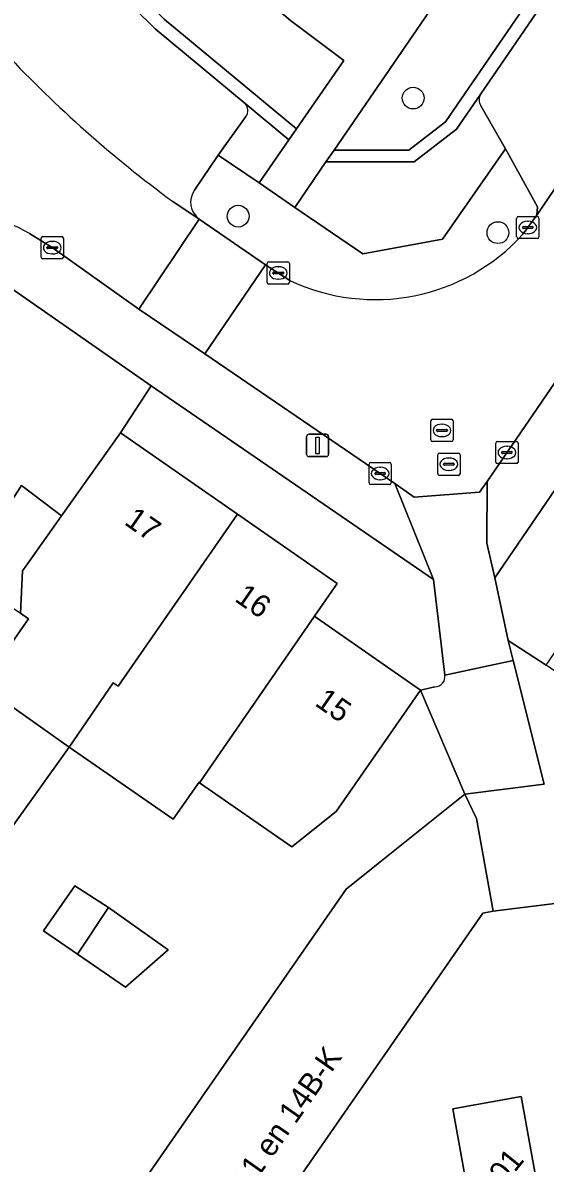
# Model space of a CAD drawing. Extents: x 159664 to 160323, y 385312 to 386115.
# Drawn here: x 160010.7 to 160034.2, y 385414.8 to 385466 of the extents above; entities that cross this region are included whole.
import ezdxf

# ---------------------------------------------------------------- set-up
doc = ezdxf.new("R2010")
doc.units = 0
for name, color, linetype in [('IMGEO_Boom', 7, 'Continuous'), ('IMGEO_Erf', 7, 'Continuous'), ('IMGEO_Groenvoorziening', 7, 'Continuous'), ('IMGEO_Haag', 7, 'Continuous'), ('IMGEO_Kolk', 7, 'Continuous'), ('IMGEO_Lichtmast', 7, 'Continuous'), ('IMGEO_Pand', 7, 'Continuous'), ('IMGEO_Pand_nummerreeks', 7, 'Continuous'), ('IMGEO_Parkeervlak_open', 7, 'Continuous'), ('IMGEO_Rijbaan_lokaal_open', 7, 'Continuous'), ('IMGEO_Rioolput', 7, 'Continuous'), ('IMGEO_Voetpad_halfverhard', 7, 'Continuous'), ('IMGEO_Voetpad_open', 7, 'Continuous')]:
    doc.layers.add(name, color=color, linetype=linetype)

msp = doc.modelspace()

# ---------------------------------------------------------------- linework, layer by layer
at = {"layer": 'IMGEO_Boom'}
for centre in [(160028.236, 385462.638), (160020.374, 385457.33), (160032.047, 385456.591)]:
    msp.add_circle(centre, 0.489, dxfattribs=at)
at = {"layer": 'IMGEO_Erf'}
for points in [[(160072.148, 385500), (160031.904, 385441.082), (160032.505, 385438.276), (160034.212, 385437.156), (160037.344, 385441.746), (160036.07, 385442.615), (160039.191, 385447.19), (160041.023, 385449.876), (160042.894, 385448.599), (160044.18, 385450.485), (160045.745, 385452.778), (160045.117, 385453.206), (160046.672, 385455.485), (160048.455, 385458.097), (160049.111, 385457.649), (160050.448, 385459.609), (160052.577, 385462.729), (160051.933, 385463.169), (160052.924, 385464.621), (160055.268, 385468.057)], [(160016.466, 385449.703), (160015.086, 385447.598), (160020.345, 385443.944), (160024.816, 385440.836), (160023.799, 385439.361), (160023.92, 385439.277), (160028.574, 385436.043), (160029.216, 385436.184)], [(160029.667, 385436.713), (160029.146, 385441.011), (160016.466, 385449.703)], [(160009.916, 385429.488), (160012.781, 385433.479), (160008.855, 385436.25), (160010.95, 385439.25), (160010.594, 385439.497)], [(160013.217, 385409.794), (160025.229, 385427.108), (160026.659, 385428.251), (160030.564, 385431.373), (160028.574, 385436.043), (160024.779, 385430.583), (160022.781, 385429.01), (160018.644, 385431.884), (160018.617, 385431.902), (160017.456, 385430.247), (160012.781, 385433.479), (160009.916, 385429.488), (160008.376, 385427.342), (160005.279, 385422.676), (160001.208, 385417.105), (159999.812, 385419.328), (159994.575, 385416.041), (159991.101, 385421.575), (159990.309, 385421.078), (159989.407, 385422.474), (159987.442, 385421.249), (159988.634, 385419.337), (159988.714, 385419.208), (159991.924, 385414.059)], [(160036.883, 385410.472), (160041.677, 385417.498), (160043.915, 385420.778), (160039.578, 385423.738), (160035.448, 385426.556), (160031.833, 385426.109), (160031.37, 385426.026), (160028.52, 385421.918), (160019.881, 385409.465)], [(160030.53, 385414.401), (160030.018, 385417.233), (160033.087, 385417.788), (160033.954, 385412.991)]]:
    msp.add_lwpolyline(points, dxfattribs=at)
for points in [[(160012.441, 385443.869), (160012.123, 385444.11), (160010.638, 385445.235), (160009.476, 385443.456), (160009.767, 385443.118), (160008.339, 385441.063), (160009.94, 385439.951), (160010.594, 385439.497), (160010.687, 385441.397), (160010.877, 385441.665)], [(160011.635, 385425.226), (160013.041, 385427.249), (160014.556, 385426.277), (160017.237, 385424.38), (160015.32, 385422.692), (160013.16, 385424.184)]]:
    msp.add_lwpolyline(points, close=True, dxfattribs=at)
msp.add_arc((160029.184, 385436.668), 0.485, 273.755, 5.3464, dxfattribs=at)
at = {"layer": 'IMGEO_Groenvoorziening'}
for points in [[(160055.672, 385498.399), (160055.902, 385498.735), (160056.092, 385498.873), (160056.047, 385499.014), (160055.612, 385499.373), (160050.555, 385503.547), (160050.123, 385503.911), (160049.605, 385503.43), (160055.296, 385498.913), (160039.454, 385475.806), (160039.424, 385475.762), (160029.696, 385461.575), (160028.045, 385460.303), (160024.69, 385460.303), (160024.321, 385459.765), (160028.283, 385459.765), (160030.191, 385461.235), (160031.278, 385462.821)], [(160039.424, 385475.762), (160039.029, 385476.11), (160030.334, 385484.884), (160028.464, 385483.131), (160035.351, 385475.859), (160024.69, 385460.303), (160028.045, 385460.303), (160029.696, 385461.575)], [(160013.62, 385474.758), (160007.747, 385482.836), (160004.704, 385480.929), (160006.534, 385477.974), (160009.493, 385474.051), (160014.257, 385468.951), (160017.05, 385466.187), (160023, 385461.258), (160025.13, 385464.325), (160022.729, 385466.121), (160019.169, 385469.159), (160018.203, 385470.052), (160017.394, 385470.882)], [(160014.257, 385468.951), (160009.493, 385474.051), (160006.534, 385477.974), (160006.055, 385477.613), (160009.031, 385473.668), (160010.584, 385471.918), (160011.823, 385470.597), (160013.835, 385468.525), (160016.647, 385465.742), (160020.691, 385462.391), (160022.656, 385460.763), (160023, 385461.258), (160017.05, 385466.187)]]:
    msp.add_lwpolyline(points, close=True, dxfattribs=at)
for points in [[(160031.278, 385462.821), (160030.191, 385461.235), (160028.283, 385459.765), (160024.321, 385459.765), (160022.923, 385457.725), (160025.969, 385455.645), (160029.554, 385456.292), (160032.387, 385460.35), (160031.274, 385462.288)], [(160020.721, 385461.806), (160019.48, 385460.076), (160021.311, 385458.826), (160022.656, 385460.763), (160020.691, 385462.391)]]:
    msp.add_lwpolyline(points, dxfattribs=at)
for centre, radius, start, end in [((160031.726, 385462.551), 0.523, 148.9326, 210.2074), ((160020.355, 385462.081), 0.457, 323.0942, 42.7772)]:
    msp.add_arc(centre, radius, start, end, dxfattribs=at)
at = {"layer": 'IMGEO_Haag'}
for points in [[(160055.672, 385498.399), (160055.902, 385498.735), (160056.092, 385498.873), (160056.047, 385499.014), (160055.612, 385499.373), (160050.555, 385503.547), (160050.123, 385503.911), (160049.605, 385503.43), (160055.296, 385498.913), (160039.454, 385475.806), (160039.424, 385475.762), (160029.696, 385461.575), (160028.045, 385460.303), (160024.69, 385460.303), (160024.321, 385459.765), (160028.283, 385459.765), (160030.191, 385461.235), (160031.278, 385462.821)], [(160014.257, 385468.951), (160009.493, 385474.051), (160006.534, 385477.974), (160006.055, 385477.613), (160009.031, 385473.668), (160010.584, 385471.918), (160011.823, 385470.597), (160013.835, 385468.525), (160016.647, 385465.742), (160020.691, 385462.391), (160022.656, 385460.763), (160023, 385461.258), (160017.05, 385466.187)]]:
    msp.add_lwpolyline(points, close=True, dxfattribs=at)
at = {"layer": 'IMGEO_Kolk'}
for p, q in [((160032.888, 385456.397), (160032.888, 385457.249)), ((160032.963, 385457.323), (160033.815, 385457.323)), ((160033.376, 385457.103), (160033.401, 385457.103)), ((160033.889, 385457.249), (160033.889, 385456.397)), ((160011.597, 385456.417), (160012.449, 385456.417)), ((160033.147, 385456.817), (160033.147, 385456.829)), ((160033.585, 385456.78), (160033.187, 385456.78)), ((160033.19, 385456.866), (160033.588, 385456.866)), ((160033.399, 385456.543), (160033.374, 385456.543)), ((160033.631, 385456.829), (160033.631, 385456.817)), ((160011.522, 385455.491), (160011.522, 385456.343)), ((160011.781, 385455.911), (160011.781, 385455.923)), ((160012.219, 385455.874), (160011.821, 385455.874)), ((160011.824, 385455.96), (160012.222, 385455.96)), ((160012.01, 385456.197), (160012.035, 385456.197)), ((160012.265, 385455.923), (160012.265, 385455.911)), ((160012.523, 385456.343), (160012.523, 385455.491)), ((160033.815, 385456.323), (160032.963, 385456.323)), ((160012.449, 385455.417), (160011.597, 385455.417)), ((160012.033, 385455.637), (160012.008, 385455.637)), ((160021.677, 385454.354), (160021.677, 385455.206)), ((160021.752, 385455.28), (160022.604, 385455.28)), ((160022.165, 385455.06), (160022.19, 385455.06)), ((160022.678, 385455.206), (160022.678, 385454.354)), ((160021.936, 385454.774), (160021.936, 385454.786)), ((160022.374, 385454.737), (160021.976, 385454.737)), ((160021.979, 385454.823), (160022.377, 385454.823)), ((160022.188, 385454.5), (160022.163, 385454.5)), ((160022.42, 385454.786), (160022.42, 385454.774)), ((160022.604, 385454.28), (160021.752, 385454.28)), ((160032.025, 385447.215), (160032.877, 385447.215)), ((160031.95, 385446.289), (160031.95, 385447.141)), ((160032.209, 385446.709), (160032.209, 385446.721)), ((160032.647, 385446.672), (160032.249, 385446.672)), ((160032.252, 385446.758), (160032.65, 385446.758)), ((160032.438, 385446.995), (160032.463, 385446.995)), ((160032.693, 385446.721), (160032.693, 385446.709)), ((160032.951, 385447.141), (160032.951, 385446.289)), ((160026.255, 385445.347), (160026.255, 385446.199)), ((160026.33, 385446.273), (160027.182, 385446.273)), ((160027.256, 385446.199), (160027.256, 385445.347)), ((160032.877, 385446.215), (160032.025, 385446.215)), ((160032.461, 385446.435), (160032.436, 385446.435)), ((160026.514, 385445.767), (160026.514, 385445.779)), ((160026.952, 385445.73), (160026.554, 385445.73)), ((160026.557, 385445.816), (160026.955, 385445.816)), ((160026.743, 385446.053), (160026.768, 385446.053)), ((160026.998, 385445.779), (160026.998, 385445.767)), ((160027.182, 385445.273), (160026.33, 385445.273)), ((160026.766, 385445.493), (160026.741, 385445.493))]:
    msp.add_line(p, q, dxfattribs=at)
for points in [[(160032.888, 385456.397), (160032.888, 385457.249)], [(160032.963, 385457.323), (160033.815, 385457.323)], [(160033.889, 385457.249), (160033.889, 385456.397)], [(160011.597, 385456.417), (160012.449, 385456.417)], [(160011.522, 385455.491), (160011.522, 385456.343)], [(160012.523, 385456.343), (160012.523, 385455.491)], [(160033.815, 385456.323), (160032.963, 385456.323)], [(160012.449, 385455.417), (160011.597, 385455.417)], [(160021.677, 385454.354), (160021.677, 385455.206)], [(160021.752, 385455.28), (160022.604, 385455.28)], [(160022.678, 385455.206), (160022.678, 385454.354)], [(160022.604, 385454.28), (160021.752, 385454.28)], [(160032.025, 385447.215), (160032.877, 385447.215)], [(160031.95, 385446.289), (160031.95, 385447.141)], [(160032.951, 385447.141), (160032.951, 385446.289)], [(160026.255, 385445.347), (160026.255, 385446.199)], [(160026.33, 385446.273), (160027.182, 385446.273)], [(160027.256, 385446.199), (160027.256, 385445.347)], [(160032.877, 385446.215), (160032.025, 385446.215)], [(160027.182, 385445.273), (160026.33, 385445.273)]]:
    msp.add_lwpolyline(points, dxfattribs=at)
for centre, radius, start, end in [((160032.965, 385457.247), 0.0765, 91.552, 178.448), ((160032.965, 385457.247), 0.0765, 91.552, 178.448), ((160033.813, 385457.247), 0.0765, 1.552, 88.448), ((160033.813, 385457.247), 0.0765, 1.552, 88.448), ((160011.599, 385456.341), 0.0765, 91.552, 178.448), ((160011.599, 385456.341), 0.0765, 91.552, 178.448), ((160012.447, 385456.341), 0.0765, 1.552, 88.448), ((160012.447, 385456.341), 0.0765, 1.552, 88.448), ((160032.965, 385456.399), 0.0765, 181.552, 268.448), ((160032.965, 385456.399), 0.0765, 181.552, 268.448), ((160033.187, 385456.826), 0.0403, 85.8775, 175.7526), ((160033.184, 385456.816), 0.0366, 178.938, 274.7102), ((160033.588, 385456.823), 0.043, 264.8664, 352.4533), ((160033.592, 385456.828), 0.0386, 1.7309, 96.639), ((160033.813, 385456.399), 0.0765, 271.552, 358.448), ((160033.813, 385456.399), 0.0765, 271.552, 358.448), ((160011.821, 385455.92), 0.0403, 85.8775, 175.7526), ((160011.818, 385455.91), 0.0366, 178.938, 274.7102), ((160012.222, 385455.917), 0.043, 264.8664, 352.4533), ((160012.226, 385455.922), 0.0386, 1.7309, 96.639), ((160011.599, 385455.493), 0.0765, 181.552, 268.448), ((160011.599, 385455.493), 0.0765, 181.552, 268.448), ((160012.447, 385455.493), 0.0765, 271.552, 358.448), ((160012.447, 385455.493), 0.0765, 271.552, 358.448), ((160021.754, 385455.204), 0.0765, 91.552, 178.448), ((160021.754, 385455.204), 0.0765, 91.552, 178.448), ((160022.602, 385455.204), 0.0765, 1.552, 88.448), ((160022.602, 385455.204), 0.0765, 1.552, 88.448), ((160021.754, 385454.356), 0.0765, 181.552, 268.448), ((160021.754, 385454.356), 0.0765, 181.552, 268.448), ((160021.976, 385454.783), 0.0403, 85.8775, 175.7526), ((160021.973, 385454.773), 0.0366, 178.938, 274.7102), ((160022.377, 385454.78), 0.043, 264.8664, 352.4533), ((160022.381, 385454.785), 0.0386, 1.7309, 96.639), ((160022.602, 385454.356), 0.0765, 271.552, 358.448), ((160022.602, 385454.356), 0.0765, 271.552, 358.448), ((160032.027, 385447.139), 0.0765, 91.552, 178.448), ((160032.027, 385447.139), 0.0765, 91.552, 178.448), ((160032.875, 385447.139), 0.0765, 1.552, 88.448), ((160032.875, 385447.139), 0.0765, 1.552, 88.448), ((160032.249, 385446.718), 0.0403, 85.8775, 175.7526), ((160032.246, 385446.708), 0.0366, 178.938, 274.7102), ((160032.65, 385446.715), 0.043, 264.8664, 352.4533), ((160032.654, 385446.72), 0.0386, 1.7309, 96.639), ((160026.332, 385446.197), 0.0765, 91.552, 178.448), ((160026.332, 385446.197), 0.0765, 91.552, 178.448), ((160027.18, 385446.197), 0.0765, 1.552, 88.448), ((160027.18, 385446.197), 0.0765, 1.552, 88.448), ((160032.027, 385446.291), 0.0765, 181.552, 268.448), ((160032.027, 385446.291), 0.0765, 181.552, 268.448), ((160032.875, 385446.291), 0.0765, 271.552, 358.448), ((160032.875, 385446.291), 0.0765, 271.552, 358.448), ((160026.554, 385445.776), 0.0403, 85.8775, 175.7526), ((160026.551, 385445.766), 0.0366, 178.938, 274.7102), ((160026.955, 385445.773), 0.043, 264.8664, 352.4533), ((160026.959, 385445.778), 0.0386, 1.7309, 96.639), ((160026.332, 385445.349), 0.0765, 181.552, 268.448), ((160026.332, 385445.349), 0.0765, 181.552, 268.448), ((160027.18, 385445.349), 0.0765, 271.552, 358.448), ((160027.18, 385445.349), 0.0765, 271.552, 358.448)]:
    msp.add_arc(centre, radius, start, end, dxfattribs=at)
for centre, major_axis, ratio, start_param, end_param in [((160033.375, 385456.823), (-0.387, 0.002), 0.722429, 4.712389, 7.853982), ((160033.4, 385456.823), (-0.39, 0.002), 0.717154, 1.570796, 4.712389), ((160012.009, 385455.917), (-0.387, 0.002), 0.722429, 4.712389, 7.853982), ((160012.034, 385455.917), (-0.39, 0.002), 0.717154, 1.570796, 4.712389), ((160022.164, 385454.78), (-0.387, 0.002), 0.722429, 4.712389, 7.853982), ((160022.189, 385454.78), (-0.39, 0.002), 0.717154, 1.570796, 4.712389), ((160032.437, 385446.715), (-0.387, 0.002), 0.722429, 4.712389, 7.853982), ((160032.462, 385446.715), (-0.39, 0.002), 0.717154, 1.570796, 4.712389), ((160026.742, 385445.773), (-0.387, 0.002), 0.722429, 4.712389, 7.853982), ((160026.767, 385445.773), (-0.39, 0.002), 0.717154, 1.570796, 4.712389)]:
    msp.add_ellipse(centre, major_axis=major_axis, ratio=ratio, start_param=start_param, end_param=end_param, dxfattribs=at)
at = {"layer": 'IMGEO_Lichtmast'}
for p, q in [((160023.445, 385446.632), (160023.445, 385447.432)), ((160023.445, 385447.432), (160023.445, 385446.632)), ((160023.545, 385447.532), (160024.335, 385447.532)), ((160024.335, 385447.532), (160023.545, 385447.532)), ((160024.435, 385447.432), (160024.435, 385446.632)), ((160024.435, 385446.632), (160024.435, 385447.432)), ((160024.335, 385446.532), (160023.545, 385446.532)), ((160023.545, 385446.532), (160024.335, 385446.532))]:
    msp.add_line(p, q, dxfattribs=at)
msp.add_lwpolyline([(160023.865, 385447.407), (160024.015, 385447.407), (160024.015, 385446.657), (160023.865, 385446.657), (160023.865, 385447.407)], dxfattribs=at)
for centre, start, end in [((160023.545, 385447.432), 90, 180), ((160023.545, 385447.432), 90, 180), ((160024.335, 385447.432), 0, 90), ((160024.335, 385447.432), 360, 90), ((160023.545, 385446.632), 180, 270), ((160023.545, 385446.632), 180, 270), ((160024.335, 385446.632), 270, 0), ((160024.335, 385446.632), 270, 0)]:
    msp.add_arc(centre, 0.1, start, end, dxfattribs=at)
at = {"layer": 'IMGEO_Pand'}
for points in [[(160016.466, 385449.703), (160008.838, 385455.005), (160006.864, 385454.76), (160002.957, 385451.018), (160009.476, 385443.456), (160010.638, 385445.235), (160012.123, 385444.11), (160012.441, 385443.869), (160015.086, 385447.598)], [(160020.345, 385443.944), (160015.086, 385447.598), (160012.441, 385443.869), (160010.877, 385441.665), (160010.687, 385441.397), (160010.594, 385439.497), (160010.95, 385439.25), (160008.855, 385436.25), (160012.781, 385433.479), (160014.753, 385436.375), (160014.978, 385436.219)], [(160023.799, 385439.361), (160024.816, 385440.836), (160020.345, 385443.944), (160014.978, 385436.219), (160014.753, 385436.375), (160012.781, 385433.479), (160017.456, 385430.247), (160018.617, 385431.902), (160018.644, 385431.884), (160019.572, 385433.23)], [(160028.574, 385436.043), (160023.92, 385439.277), (160023.799, 385439.361), (160019.572, 385433.23), (160018.644, 385431.884), (160022.781, 385429.01), (160024.779, 385430.583)], [(160020.872, 385403.98), (160019.881, 385409.465), (160028.52, 385421.918), (160031.37, 385426.026), (160031.833, 385426.109), (160031.079, 385430.28), (160030.564, 385431.373), (160026.659, 385428.251), (160025.229, 385427.108), (160013.217, 385409.794), (160009.555, 385404.58), (160013.629, 385403.801), (160016.028, 385401.013), (160016.494, 385396.736), (160015.015, 385394.604), (160017.883, 385389.891), (160017.969, 385390.015), (160022.284, 385396.172)], [(160014.556, 385426.277), (160013.041, 385427.249), (160011.635, 385425.226), (160013.16, 385424.184)], [(160017.237, 385424.38), (160014.556, 385426.277), (160013.16, 385424.184), (160015.32, 385422.692)], [(160031.44, 385409.368), (160033.954, 385412.991), (160033.087, 385417.788), (160030.018, 385417.233), (160030.53, 385414.401)]]:
    msp.add_lwpolyline(points, close=True, dxfattribs=at)
at = {"layer": 'IMGEO_Parkeervlak_open'}
for points in [[(160031.274, 385462.288), (160032.387, 385460.35), (160033.828, 385457.753), (160033.788, 385457.377), (160048.49, 385479.009), (160050.513, 385481.978), (160069.015, 385509.049)], [(160056.092, 385498.873), (160055.902, 385498.735), (160055.672, 385498.399), (160031.278, 385462.821)], [(160016.647, 385465.742), (160013.835, 385468.525), (160011.823, 385470.597), (160010.584, 385471.918), (160009.031, 385473.668), (160006.055, 385477.613)], [(160020.691, 385462.391), (160016.647, 385465.742)], [(160018.413, 385458.5), (160019.48, 385460.076), (160020.721, 385461.806)], [(160017.439, 385457.988), (160018.63, 385457.2)]]:
    msp.add_lwpolyline(points, dxfattribs=at)
for centre, radius, start, end in [((160051.118, 385503.581), 56.684, 223.3755, 233.5468), ((160031.726, 385462.551), 0.523, 148.9326, 210.2074), ((160020.355, 385462.081), 0.457, 323.0942, 42.7772), ((160019.174, 385457.959), 0.934, 144.5834, 234.3698)]:
    msp.add_arc(centre, radius, start, end, dxfattribs=at)
at = {"layer": 'IMGEO_Rijbaan_lokaal_open'}
for points in [[(160048.49, 385479.009), (160033.788, 385457.377)], [(160031.557, 385445.41), (160052.619, 385476.171)], [(160010.997, 385456.554), (160012.023, 385455.917), (160015.918, 385453.149), (160018.63, 385457.2), (160017.439, 385457.988)], [(160033.788, 385457.377), (160033.183, 385456.537)], [(160021.61, 385455.146), (160018.875, 385451.146)], [(160022.693, 385454.449), (160021.61, 385455.146)], [(160018.875, 385451.146), (160027.414, 385445.324)], [(160027.414, 385445.324), (160027.919, 385444.964)], [(160027.919, 385444.964), (160028.285, 385444.702), (160031.218, 385444.93), (160031.557, 385445.41)], [(160029.216, 385436.184), (160028.574, 385436.043), (160030.564, 385431.373), (160034.128, 385431.814), (160032.732, 385437.373), (160029.667, 385436.713)]]:
    msp.add_lwpolyline(points, dxfattribs=at)
for points in [[(160018.875, 385451.146), (160021.61, 385455.146), (160018.63, 385457.2), (160015.918, 385453.149)], [(160032.732, 385437.373), (160034.128, 385431.814), (160030.564, 385431.373), (160031.079, 385430.28), (160031.833, 385426.109), (160035.448, 385426.556), (160034.754, 385432.66), (160036.675, 385435.475), (160034.212, 385437.156), (160032.505, 385438.276)]]:
    msp.add_lwpolyline(points, close=True, dxfattribs=at)
for centre, radius, start, end in [((160051.118, 385503.581), 56.684, 223.3755, 233.5468), ((160007.778, 385451.081), 6.35, 59.5382, 138.1523), ((160026.535, 385462.543), 8.96, 244.6095, 317.9053), ((160029.184, 385436.668), 0.485, 273.755, 5.3464)]:
    msp.add_arc(centre, radius, start, end, dxfattribs=at)
at = {"layer": 'IMGEO_Rioolput'}
for p, q in [((160029.108, 385448.208), (160029.96, 385448.208)), ((160029.033, 385447.282), (160029.033, 385448.134)), ((160029.292, 385447.702), (160029.292, 385447.714)), ((160029.335, 385447.751), (160029.733, 385447.751)), ((160029.521, 385447.988), (160029.546, 385447.988)), ((160029.776, 385447.714), (160029.776, 385447.702)), ((160030.034, 385448.134), (160030.034, 385447.282)), ((160029.96, 385447.208), (160029.108, 385447.208)), ((160029.73, 385447.665), (160029.332, 385447.665)), ((160029.544, 385447.428), (160029.519, 385447.428)), ((160029.417, 385446.689), (160030.269, 385446.689)), ((160029.342, 385445.763), (160029.342, 385446.615)), ((160029.601, 385446.183), (160029.601, 385446.195)), ((160030.039, 385446.146), (160029.641, 385446.146)), ((160029.644, 385446.232), (160030.042, 385446.232)), ((160029.83, 385446.469), (160029.855, 385446.469)), ((160030.085, 385446.195), (160030.085, 385446.183)), ((160030.343, 385446.615), (160030.343, 385445.763)), ((160030.269, 385445.689), (160029.417, 385445.689)), ((160029.853, 385445.909), (160029.828, 385445.909))]:
    msp.add_line(p, q, dxfattribs=at)
for points in [[(160029.108, 385448.208), (160029.96, 385448.208)], [(160029.033, 385447.282), (160029.033, 385448.134)], [(160030.034, 385448.134), (160030.034, 385447.282)], [(160029.96, 385447.208), (160029.108, 385447.208)], [(160029.417, 385446.689), (160030.269, 385446.689)], [(160029.342, 385445.763), (160029.342, 385446.615)], [(160030.343, 385446.615), (160030.343, 385445.763)], [(160030.269, 385445.689), (160029.417, 385445.689)]]:
    msp.add_lwpolyline(points, dxfattribs=at)
for centre, radius, start, end in [((160029.11, 385448.132), 0.0765, 91.552, 178.448), ((160029.11, 385448.132), 0.0765, 91.552, 178.448), ((160029.958, 385448.132), 0.0765, 1.552, 88.448), ((160029.958, 385448.132), 0.0765, 1.552, 88.448), ((160029.332, 385447.711), 0.0403, 85.8775, 175.7526), ((160029.329, 385447.701), 0.0366, 178.938, 274.7102), ((160029.733, 385447.708), 0.043, 264.8664, 352.4533), ((160029.737, 385447.713), 0.0386, 1.7309, 96.639), ((160029.11, 385447.284), 0.0765, 181.552, 268.448), ((160029.11, 385447.284), 0.0765, 181.552, 268.448), ((160029.958, 385447.284), 0.0765, 271.552, 358.448), ((160029.958, 385447.284), 0.0765, 271.552, 358.448), ((160029.419, 385446.613), 0.0765, 91.552, 178.448), ((160029.419, 385446.613), 0.0765, 91.552, 178.448), ((160030.267, 385446.613), 0.0765, 1.552, 88.448), ((160030.267, 385446.613), 0.0765, 1.552, 88.448), ((160029.641, 385446.192), 0.0403, 85.8775, 175.7526), ((160029.638, 385446.182), 0.0366, 178.938, 274.7102), ((160030.042, 385446.189), 0.043, 264.8664, 352.4533), ((160030.046, 385446.194), 0.0386, 1.7309, 96.639), ((160029.419, 385445.765), 0.0765, 181.552, 268.448), ((160029.419, 385445.765), 0.0765, 181.552, 268.448), ((160030.267, 385445.765), 0.0765, 271.552, 358.448), ((160030.267, 385445.765), 0.0765, 271.552, 358.448)]:
    msp.add_arc(centre, radius, start, end, dxfattribs=at)
for centre, major_axis, ratio, start_param, end_param in [((160029.52, 385447.708), (-0.387, 0.002), 0.722429, 4.712389, 7.853982), ((160029.545, 385447.708), (-0.39, 0.002), 0.717154, 1.570796, 4.712389), ((160029.829, 385446.189), (-0.387, 0.002), 0.722429, 4.712389, 7.853982), ((160029.854, 385446.189), (-0.39, 0.002), 0.717154, 1.570796, 4.712389)]:
    msp.add_ellipse(centre, major_axis=major_axis, ratio=ratio, start_param=start_param, end_param=end_param, dxfattribs=at)
at = {"layer": 'IMGEO_Voetpad_halfverhard'}
msp.add_lwpolyline([(160013.959, 385485.341), (160022.604, 385478.596), (160017.394, 385470.882), (160018.203, 385470.052), (160019.169, 385469.159), (160022.729, 385466.121), (160025.13, 385464.325), (160023, 385461.258), (160022.656, 385460.763), (160021.311, 385458.826), (160022.923, 385457.725), (160024.321, 385459.765), (160024.69, 385460.303), (160035.351, 385475.859), (160028.464, 385483.131), (160030.334, 385484.884), (160030.679, 385485.214), (160047.744, 385501.701)], dxfattribs=at)
at = {"layer": 'IMGEO_Voetpad_open'}
for points in [[(160074.794, 385508.563), (160074.312, 385507.86), (160071.889, 385504.341), (160072.872, 385503.661), (160070.504, 385500.161), (160069.511, 385500.833), (160054.637, 385479.095), (160052.619, 385476.171), (160031.557, 385445.41), (160031.552, 385442.648), (160031.904, 385441.082), (160072.148, 385500)], [(160033.183, 385456.537), (160033.788, 385457.377), (160033.828, 385457.753), (160032.387, 385460.35), (160029.554, 385456.292), (160025.969, 385455.645), (160022.923, 385457.725), (160021.311, 385458.826), (160019.48, 385460.076), (160018.413, 385458.5)], [(160018.63, 385457.2), (160021.61, 385455.146), (160022.693, 385454.449)], [(159982.481, 385433.458), (159983.316, 385433.977), (159988.553, 385437.264), (159989.296, 385437.935), (159997.713, 385445.996), (160002.957, 385451.018), (160006.864, 385454.76), (160008.838, 385455.005), (160016.466, 385449.703), (160029.146, 385441.011), (160027.414, 385445.324), (160018.875, 385451.146), (160015.918, 385453.149), (160012.023, 385455.917), (160010.997, 385456.554)]]:
    msp.add_lwpolyline(points, dxfattribs=at)
msp.add_lwpolyline([(160029.146, 385441.011), (160029.667, 385436.713), (160032.732, 385437.373), (160032.505, 385438.276), (160031.904, 385441.082), (160031.552, 385442.648), (160031.557, 385445.41), (160031.218, 385444.93), (160028.285, 385444.702), (160027.919, 385444.964), (160027.414, 385445.324)], close=True, dxfattribs=at)
for centre, radius, start, end in [((160019.174, 385457.959), 0.934, 144.5834, 234.3698), ((160007.778, 385451.081), 6.35, 59.5382, 138.1523), ((160026.535, 385462.543), 8.96, 244.6095, 317.9053)]:
    msp.add_arc(centre, radius, start, end, dxfattribs=at)

# ---------------------------------------------------------------- texts
at = {"layer": 'IMGEO_Pand_nummerreeks'}
for s, rotation, p in [('17', 325.2043, (160015.211, 385443.516)), ('16', 325.2043, (160020.167, 385440.072)), ('15', 325.2043, (160023.771, 385435.386)), ('14/G06-14/G11 en 14B-K', 55.0498, (160016.389, 385407.129)), ('14/G01', 51.1155, (160030.513, 385411.511))]:
    msp.add_text(s, height=1, rotation=rotation, dxfattribs=at).set_placement(p)

doc.saveas('drawing.dxf')
